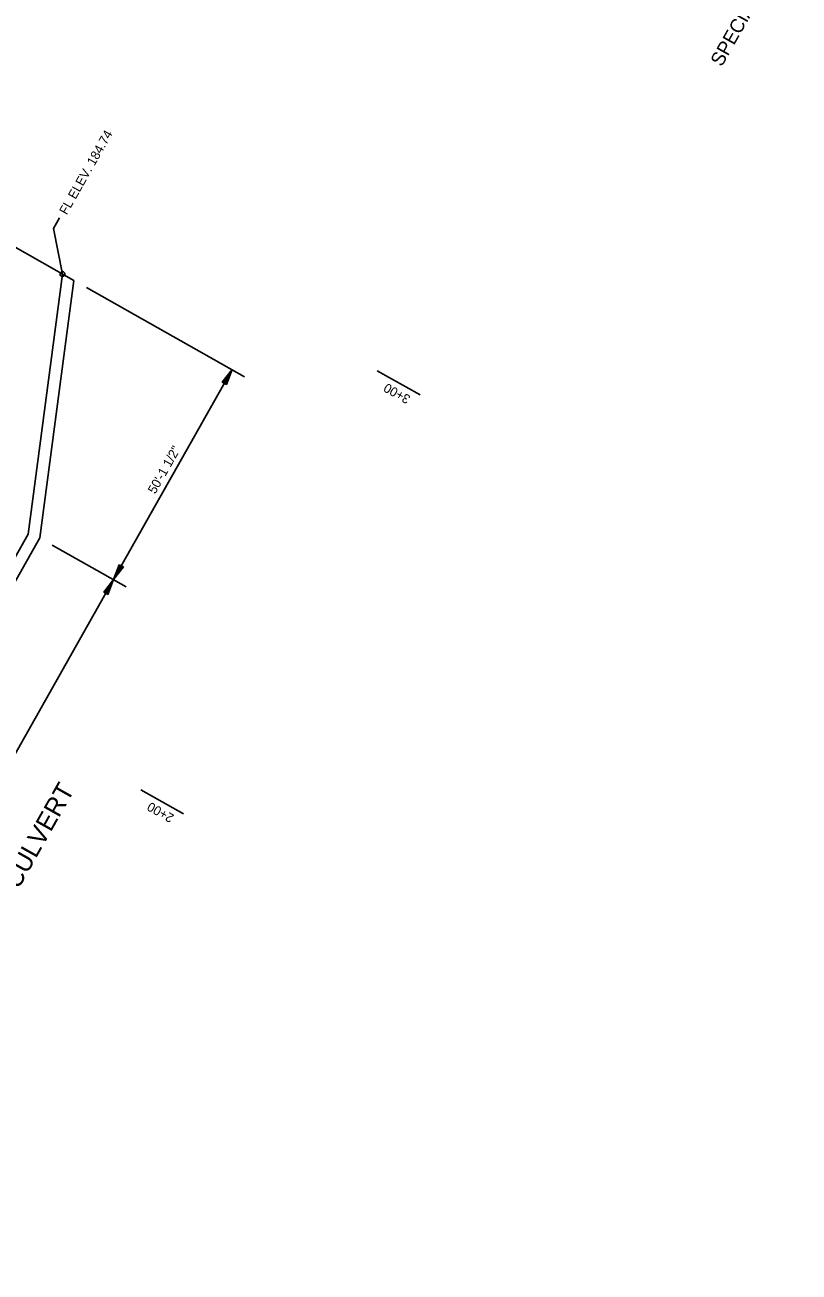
# Model space of a CAD drawing. Extents: x 992322 to 992796, y 1839560 to 1840070.
# Drawn here: x 992635.5 to 992796.4, y 1839640.5 to 1839899.8 of the extents above; entities that cross this region are included whole.
import ezdxf

# ---------------------------------------------------------------- set-up
doc = ezdxf.new("R2010")
doc.units = 0
for name, color, linetype in [('60', 7, 'Continuous'), ('B-Gen-Dimension', 7, 'Continuous'), ('B-Gen-Hidden', 7, 'Continuous'), ('B-Gen-Object', 7, 'Continuous'), ('Default', 7, 'Continuous'), ('R_Draft', 7, 'Continuous')]:
    doc.layers.add(name, color=color, linetype=linetype)

msp = doc.modelspace()

# ---------------------------------------------------------------- linework, layer by layer
at = {"layer": 'B-Gen-Dimension'}
msp.add_circle((992643.3, 1839847.98), 0.5, dxfattribs=at)
at = {"layer": 'B-Gen-Hidden'}
for p in [(992643.3, 1839847.98), (992557.12, 1839653.87)]:
    msp.add_line(p, (992636.14, 1839793.9), dxfattribs=at)
at = {"layer": 'B-Gen-Object'}
for p, q in [((992645.65, 1839846.66), (992632.49, 1839854.09)), ((992645.65, 1839846.66), (992638.56, 1839793.1)), ((992559.12, 1839652.32), (992638.56, 1839793.1))]:
    msp.add_line(p, q, dxfattribs=at)
at = {"layer": 'R_Draft'}
for p, q in [((992642.69, 1839859.67), (992641.44, 1839857.45)), ((992641.44, 1839857.45), (992643.3, 1839847.98)), ((992648.26, 1839845.18), (992681.15, 1839826.62)), ((992653.9, 1839784.45), (992678.54, 1839828.1)), ((992676.49, 1839825.48), (992678.54, 1839828.1)), ((992676.56, 1839825.44), (992678.27, 1839827.62)), ((992676.64, 1839825.4), (992677.99, 1839827.13)), ((992676.7, 1839825.36), (992677.72, 1839826.65)), ((992676.79, 1839825.31), (992677.45, 1839826.17)), ((992677.06, 1839825.15), (992677.45, 1839826.17)), ((992677.13, 1839825.12), (992677.72, 1839826.65)), ((992677.21, 1839825.07), (992677.99, 1839827.13)), ((992677.28, 1839825.03), (992678.27, 1839827.62)), ((992677.35, 1839824.99), (992678.54, 1839828.1)), ((992708.71, 1839827.86), (992717.6, 1839822.85)), ((992676.49, 1839825.48), (992677.35, 1839824.99)), ((992676.85, 1839825.27), (992677.18, 1839825.69)), ((992676.99, 1839825.2), (992677.18, 1839825.69)), ((992641.18, 1839791.63), (992656.51, 1839782.97)), ((992655.09, 1839787.55), (992653.9, 1839784.45)), ((992655.95, 1839787.07), (992653.9, 1839784.45)), ((992655.16, 1839787.51), (992654.17, 1839784.92)), ((992655.87, 1839787.11), (992654.17, 1839784.92)), ((992655.23, 1839787.47), (992654.45, 1839785.42)), ((992655.8, 1839787.15), (992654.45, 1839785.42)), ((992655.3, 1839787.43), (992654.72, 1839785.89)), ((992655.73, 1839787.19), (992654.72, 1839785.89)), ((992655.38, 1839787.38), (992654.99, 1839786.38)), ((992655.66, 1839787.23), (992654.99, 1839786.38)), ((992655.09, 1839787.55), (992655.95, 1839787.07)), ((992655.45, 1839787.35), (992655.26, 1839786.85)), ((992655.59, 1839787.27), (992655.26, 1839786.85)), ((992574.45, 1839643.67), (992654.2, 1839784.98)), ((992651.86, 1839781.82), (992653.9, 1839784.45)), ((992652.71, 1839781.34), (992653.9, 1839784.45)), ((992651.93, 1839781.78), (992653.63, 1839783.97)), ((992652, 1839781.74), (992653.35, 1839783.48)), ((992652.07, 1839781.7), (992653.08, 1839783)), ((992652.15, 1839781.66), (992652.81, 1839782.51)), ((992652.22, 1839781.62), (992652.54, 1839782.04)), ((992652.35, 1839781.54), (992652.54, 1839782.04)), ((992652.43, 1839781.5), (992652.81, 1839782.51)), ((992652.5, 1839781.46), (992653.08, 1839783)), ((992652.57, 1839781.42), (992653.35, 1839783.48)), ((992652.64, 1839781.38), (992653.63, 1839783.97)), ((992651.86, 1839781.82), (992652.71, 1839781.34)), ((992659.57, 1839740.77), (992668.45, 1839735.76))]:
    msp.add_line(p, q, dxfattribs=at)

# ---------------------------------------------------------------- texts
at = {"layer": '60'}
msp.add_text('SPECIAL DETAILS', height=2.88, rotation=60.5619, dxfattribs=at).set_placement((992780.31, 1839890.93))
at = {"layer": 'Default'}
msp.add_text('PROFILE - QUINTUPLE BARREL BOX CULVERT', height=3.84, rotation=60.5619, dxfattribs=at).set_placement((992589.09, 1839640.11))
at = {"layer": 'R_Draft'}
for s, rotation, p in [('FL ELEV. 184.74', 60.5619, (992644.17, 1839860.16)), ('3+00', 150.5619, (992715.79, 1839822.54)), ('50\'-1 1/2"', 60.5619, (992662.58, 1839802.12)), ('2+00', 150.5619, (992666.64, 1839735.45))]:
    msp.add_text(s, height=1.92, rotation=rotation, dxfattribs=at).set_placement(p)

doc.saveas('drawing.dxf')
